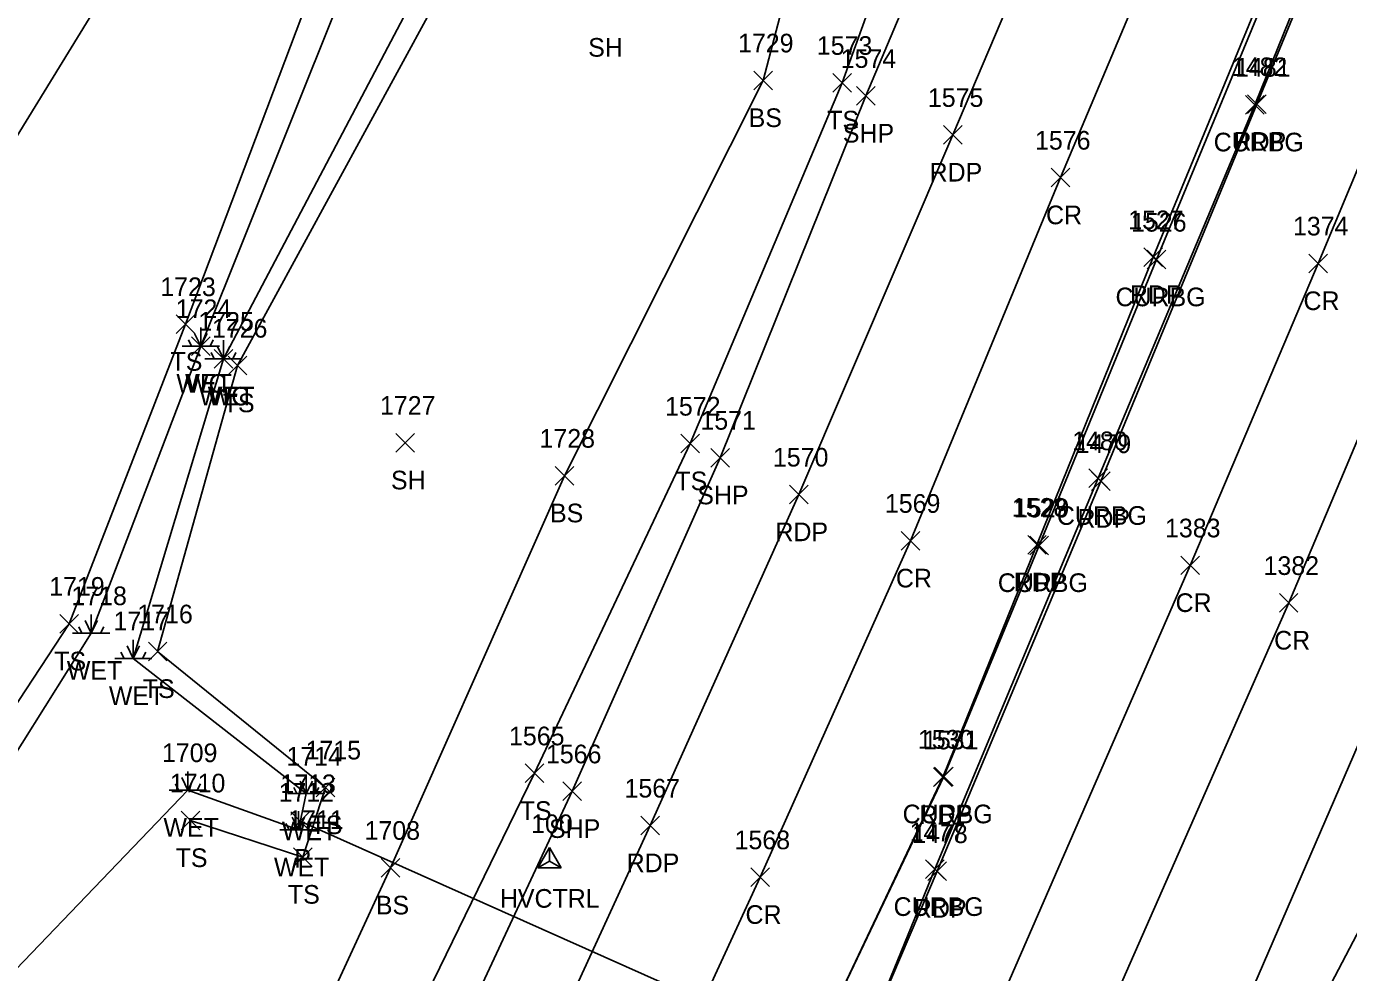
# Model space of a CAD drawing. Extents: x 1623612 to 1625808, y 621345 to 627748.
# Drawn here: x 1624457.2 to 1624599, y 625894.9 to 625996.3 of the extents above; entities that cross this region are included whole.
import ezdxf

# ---------------------------------------------------------------- set-up
doc = ezdxf.new("R2010")
doc.units = 0
for name, color, linetype in [('C_A', 7, 'Continuous'), ('C_I', 7, 'Continuous'), ('CPSM', 7, 'Continuous'), ('D_A', 7, 'Continuous'), ('D_I', 7, 'Continuous'), ('D_TIC', 7, 'Continuous'), ('DCP', 7, 'Continuous'), ('L_A', 7, 'Continuous'), ('L_I', 7, 'Continuous'), ('L_TIC', 7, 'Continuous'), ('LAWE', 7, 'Continuous'), ('LELB', 7, 'Continuous'), ('LFNC', 7, 'Continuous'), ('LSOGP', 7, 'Continuous'), ('LWET', 7, 'Continuous'), ('P_A', 7, 'Continuous'), ('P_I', 7, 'Continuous'), ('P_TIC', 7, 'Continuous'), ('PET', 7, 'Continuous'), ('PRC', 7, 'Continuous'), ('PSP', 7, 'Continuous'), ('R_A', 7, 'Continuous'), ('R_I', 7, 'Continuous'), ('R_TIC', 7, 'Continuous'), ('RC', 7, 'Continuous')]:
    doc.layers.add(name, color=color, linetype=linetype)

msp = doc.modelspace()

# ---------------------------------------------------------------- linework, layer by layer
at = {"layer": 'CPSM'}
for p, q in [((1624512.03, 625906.07), (1624513.28, 625908.24)), ((1624514.53, 625906.07), (1624513.28, 625908.24)), ((1624513.28, 625906.8), (1624513.28, 625908.24)), ((1624512.03, 625906.07), (1624513.28, 625906.8)), ((1624512.03, 625906.07), (1624514.53, 625906.07)), ((1624513.28, 625906.8), (1624513.28, 625906.8)), ((1624513.28, 625906.8), (1624514.53, 625906.07))]:
    msp.add_line(p, q, dxfattribs=at)
at = {"layer": 'D_TIC'}
for points in [[(1624485.55, 625910.08), (1624487.55, 625912.08)], [(1624487.55, 625910.08), (1624485.55, 625912.08)]]:
    msp.add_lwpolyline(points, dxfattribs=at)
at = {"layer": 'DCP'}
msp.add_lwpolyline([(1624543.09, 625885.86), (1624486.55, 625911.08)], dxfattribs=at)
at = {"layer": 'L_TIC'}
for points in [[(1624535.21, 625989.48), (1624537.21, 625991.48)], [(1624537.21, 625989.48), (1624535.21, 625991.48)], [(1624543.66, 625989.22), (1624545.66, 625991.22)], [(1624545.66, 625989.22), (1624543.66, 625991.22)], [(1624473.24, 625963.36), (1624475.24, 625965.36)], [(1624475.24, 625963.36), (1624473.24, 625965.36)], [(1624474.9, 625961), (1624476.9, 625963)], [(1624476.9, 625961), (1624474.9, 625963)], [(1624477.34, 625959.64), (1624479.34, 625961.64)], [(1624479.34, 625959.64), (1624477.34, 625961.64)], [(1624478.84, 625958.91), (1624480.84, 625960.91)], [(1624480.84, 625958.91), (1624478.84, 625960.91)], [(1624496.8, 625950.64), (1624498.8, 625952.64)], [(1624498.8, 625950.64), (1624496.8, 625952.64)], [(1624527.38, 625950.55), (1624529.38, 625952.55)], [(1624529.38, 625950.55), (1624527.38, 625952.55)], [(1624513.91, 625947.11), (1624515.91, 625949.11)], [(1624515.91, 625947.11), (1624513.91, 625949.11)], [(1624460.77, 625931.24), (1624462.77, 625933.24)], [(1624462.77, 625931.24), (1624460.77, 625933.24)], [(1624470.27, 625928.28), (1624472.27, 625930.28)], [(1624472.27, 625928.28), (1624470.27, 625930.28)], [(1624510.69, 625915.21), (1624512.69, 625917.21)], [(1624512.69, 625915.21), (1624510.69, 625917.21)], [(1624488.26, 625913.69), (1624490.26, 625915.69)], [(1624490.26, 625913.69), (1624488.26, 625915.69)], [(1624473.79, 625910.16), (1624475.79, 625912.16)], [(1624475.79, 625910.16), (1624473.79, 625912.16)], [(1624485.83, 625906.23), (1624487.83, 625908.23)], [(1624487.83, 625906.23), (1624485.83, 625908.23)], [(1624495.23, 625905.08), (1624497.23, 625907.08)], [(1624497.23, 625905.08), (1624495.23, 625907.08)]]:
    msp.add_lwpolyline(points, dxfattribs=at)
at = {"layer": 'LAWE'}
for points in [[(1624478.34, 625960.64), (1624502.51, 626006.49), (1624510.02, 626033.48), (1624538.01, 626022.07), (1624539, 626026.11), (1624515.37, 626039.01), (1624525.82, 626080.12), (1624541.49, 626122.12), (1624557.13, 626161.32), (1624574.3, 626199.4), (1624588.96, 626242.23), (1624604.56, 626282.04), (1624612.69, 626318.46), (1624618.16, 626354.23), (1624633.32, 626339.44), (1624651.01, 626315.35), (1624653.64, 626319.94), (1624637.21, 626339.9), (1624620.54, 626359.04), (1624606.22, 626380.55), (1624599.51, 626405.02), (1624601.1, 626417.17), (1624599.39, 626418.68), (1624597.72, 626417.92)], [(1624475.9, 625962), (1624495.4, 626010.74), (1624513.45, 626053.64), (1624523.83, 626080.72), (1624539.75, 626122.53), (1624554.03, 626163.77), (1624569.78, 626201.47), (1624586.16, 626244.06), (1624600.64, 626283.77), (1624605.98, 626319.56), (1624614.72, 626357.4), (1624602.68, 626377.24), (1624598.91, 626387.68), (1624595.49, 626400.19), (1624596.27, 626415.38)]]:
    msp.add_lwpolyline(points, dxfattribs=at)
at = {"layer": 'LELB'}
for points in [[(1624405.5, 625728.14), (1624428.24, 625773.19), (1624451.7, 625813.41), (1624479.3, 625869.39), (1624496.23, 625906.08), (1624514.91, 625948.11), (1624536.21, 625990.48), (1624546.45, 626029.66), (1624561.04, 626063.21), (1624576.65, 626110.9), (1624590.48, 626147.32), (1624609.26, 626181.73), (1624628.06, 626219.01), (1624648.51, 626267.43), (1624661.85, 626303.08), (1624661.36, 626343.87), (1624651.86, 626347.04), (1624650.32, 626353.64), (1624652.97, 626362.16), (1624638.4, 626383.22), (1624618.17, 626397.94), (1624604.09, 626415.44)], [(1624375.32, 625803.31), (1624399.86, 625843.95), (1624436.39, 625893.65), (1624461.77, 625932.24), (1624474.24, 625964.36), (1624492.43, 626012.44), (1624506.84, 626058.35), (1624517.83, 626084.66), (1624533.25, 626127.2), (1624547.8, 626166.97), (1624564.84, 626204.52), (1624581.23, 626246.76), (1624598.57, 626285.31), (1624600.66, 626320.03), (1624610.19, 626356.83), (1624599.69, 626375.7), (1624596.69, 626386.19), (1624590.38, 626400.67)], [(1624474.79, 625911.16), (1624486.83, 625907.23), (1624489.26, 625914.69), (1624471.27, 625929.28), (1624479.84, 625959.91), (1624504.09, 626004.46), (1624515.23, 626027.37), (1624539.55, 626018.82), (1624542.04, 626026.15), (1624519.32, 626037.26), (1624532.33, 626078.05), (1624547.61, 626119.81), (1624564.25, 626158.84), (1624580.02, 626196.52), (1624593.61, 626237.98), (1624610.85, 626280.48), (1624618.75, 626317.35), (1624619.41, 626347.56)], [(1624414.82, 625722.7), (1624435.62, 625760.87), (1624453.7, 625797.23), (1624474.13, 625837.17), (1624493.41, 625878.76), (1624511.69, 625916.21), (1624528.38, 625951.55), (1624544.66, 625990.22), (1624558.02, 626027.25), (1624569.94, 626061.58), (1624576.34, 626070.61), (1624593.27, 626109.93), (1624608.95, 626149.66), (1624624.61, 626188.43), (1624639.61, 626224.64), (1624652.78, 626258.96), (1624662.63, 626284.81), (1624668.95, 626309.14), (1624669.8, 626328.28), (1624669.98, 626343.79)]]:
    msp.add_lwpolyline(points, dxfattribs=at)
at = {"layer": 'LFNC'}
msp.add_lwpolyline([(1624427.61, 625937.89), (1624449.98, 625974.47), (1624478.22, 626020.43), (1624495.88, 626064.36), (1624506.11, 626090.08), (1624523, 626131.63), (1624538.15, 626169.09), (1624554.88, 626209.48), (1624571.65, 626251.72), (1624567.39, 626290.68), (1624562.31, 626349.95), (1624561.25, 626380.14), (1624560.31, 626420.97), (1624559.52, 626449.49)], dxfattribs=at)
at = {"layer": 'LSOGP'}
msp.add_lwpolyline([(1624523, 626131.63), (1624506.11, 626090.08), (1624495.88, 626064.36), (1624478.22, 626020.43), (1624449.98, 625974.47), (1624427.61, 625937.89), (1624410.91, 625910.13), (1624379.58, 625859.99)], dxfattribs=at)
at = {"layer": 'LWET'}
for p, q in [((1624475.9, 625962), (1624475.9, 625964)), ((1624474.9, 625962), (1624474.57, 625962.67)), ((1624475.9, 625962), (1624475.23, 625963.34)), ((1624475.9, 625962), (1624476.57, 625963.34)), ((1624476.9, 625962), (1624477.23, 625962.67)), ((1624478.34, 625960.64), (1624478.34, 625962.64)), ((1624477.9, 625962), (1624473.9, 625962)), ((1624477.34, 625960.64), (1624477, 625961.31)), ((1624478.34, 625960.64), (1624477.67, 625961.97)), ((1624478.34, 625960.64), (1624479, 625961.97)), ((1624479.34, 625960.64), (1624479.67, 625961.31)), ((1624480.34, 625960.64), (1624476.34, 625960.64)), ((1624464.15, 625931.23), (1624464.15, 625933.23)), ((1624466.15, 625931.23), (1624462.15, 625931.23)), ((1624463.15, 625931.23), (1624462.81, 625931.9)), ((1624464.15, 625931.23), (1624463.48, 625932.57)), ((1624464.15, 625931.23), (1624464.81, 625932.57)), ((1624465.15, 625931.23), (1624465.48, 625931.9)), ((1624468.66, 625928.53), (1624467.99, 625929.86)), ((1624468.66, 625928.53), (1624468.66, 625930.53)), ((1624468.66, 625928.53), (1624469.33, 625929.86)), ((1624470.66, 625928.53), (1624466.66, 625928.53)), ((1624467.66, 625928.53), (1624467.33, 625929.19)), ((1624469.66, 625928.53), (1624469.99, 625929.19)), ((1624474.51, 625914.41), (1624473.85, 625915.75)), ((1624474.51, 625914.41), (1624474.51, 625916.41)), ((1624474.51, 625914.41), (1624475.18, 625915.75)), ((1624487.21, 625914.04), (1624487.21, 625916.04)), ((1624476.51, 625914.41), (1624472.51, 625914.41)), ((1624473.51, 625914.41), (1624473.18, 625915.08)), ((1624475.51, 625914.41), (1624475.85, 625915.08)), ((1624486.21, 625914.04), (1624485.87, 625914.7)), ((1624487.21, 625914.04), (1624486.54, 625915.37)), ((1624487.21, 625914.04), (1624487.87, 625915.37)), ((1624488.21, 625914.04), (1624488.54, 625914.7)), ((1624489.21, 625914.04), (1624485.21, 625914.04)), ((1624486.36, 625910.16), (1624485.7, 625911.49)), ((1624486.36, 625910.16), (1624486.36, 625912.16)), ((1624486.36, 625910.16), (1624487.03, 625911.49)), ((1624488.36, 625910.16), (1624484.36, 625910.16)), ((1624485.36, 625910.16), (1624485.03, 625910.83)), ((1624487.36, 625910.16), (1624487.7, 625910.83))]:
    msp.add_line(p, q, dxfattribs=at)
for points in [[(1624378.24, 625801.1), (1624404.77, 625840.83), (1624439.42, 625891.91), (1624464.15, 625931.23), (1624475.9, 625962)], [(1624362.47, 625753.11), (1624386.95, 625796), (1624412.3, 625837.76), (1624446.85, 625885.6), (1624474.51, 625914.41), (1624486.36, 625910.16), (1624487.21, 625914.04), (1624468.66, 625928.53), (1624478.34, 625960.64)]]:
    msp.add_lwpolyline(points, dxfattribs=at)
at = {"layer": 'P_TIC'}
for points in [[(1624546.22, 625987.82), (1624548.22, 625989.82)], [(1624548.22, 625987.82), (1624546.22, 625989.82)], [(1624588.16, 625986.94), (1624590.16, 625988.94)], [(1624590.16, 625986.94), (1624588.16, 625988.94)], [(1624555.56, 625983.64), (1624557.56, 625985.64)], [(1624557.56, 625983.64), (1624555.56, 625985.64)], [(1624567.1, 625979.06), (1624569.1, 625981.06)], [(1624569.1, 625979.06), (1624567.1, 625981.06)], [(1624577.04, 625970.53), (1624579.04, 625972.53)], [(1624579.04, 625970.53), (1624577.04, 625972.53)], [(1624594.71, 625969.86), (1624596.71, 625971.86)], [(1624596.71, 625969.86), (1624594.71, 625971.86)], [(1624530.6, 625949.04), (1624532.6, 625951.04)], [(1624532.6, 625949.04), (1624530.6, 625951.04)], [(1624571.42, 625946.53), (1624573.42, 625948.53)], [(1624573.42, 625946.53), (1624571.42, 625948.53)], [(1624539.03, 625945.09), (1624541.03, 625947.09)], [(1624541.03, 625945.09), (1624539.03, 625947.09)], [(1624551.01, 625940.13), (1624553.01, 625942.13)], [(1624553.01, 625940.13), (1624551.01, 625942.13)], [(1624564.57, 625939.71), (1624566.57, 625941.71)], [(1624566.57, 625939.71), (1624564.57, 625941.71)], [(1624581, 625937.5), (1624583, 625939.5)], [(1624583, 625937.5), (1624581, 625939.5)], [(1624591.56, 625933.47), (1624593.56, 625935.47)], [(1624593.56, 625933.47), (1624591.56, 625935.47)], [(1624554.47, 625914.78), (1624556.47, 625916.78)], [(1624556.47, 625914.78), (1624554.47, 625916.78)], [(1624514.71, 625913.28), (1624516.71, 625915.28)], [(1624516.71, 625913.28), (1624514.71, 625915.28)], [(1624523.08, 625909.61), (1624525.08, 625911.61)], [(1624525.08, 625909.61), (1624523.08, 625911.61)], [(1624534.88, 625904.07), (1624536.88, 625906.07)], [(1624536.88, 625904.07), (1624534.88, 625906.07)], [(1624553.88, 625904.73), (1624555.88, 625906.73)], [(1624555.88, 625904.73), (1624553.88, 625906.73)]]:
    msp.add_lwpolyline(points, dxfattribs=at)
at = {"layer": 'PET'}
for points in [[(1624425.67, 625715.65), (1624447.22, 625754.54), (1624466.36, 625791.08), (1624487.12, 625831.75), (1624506.3, 625871.9), (1624524.08, 625910.61), (1624540.03, 625946.09), (1624556.56, 625984.64), (1624572.71, 626022.65), (1624589.71, 626064.03), (1624605.99, 626104.3), (1624622.34, 626144.13), (1624637.91, 626182.32), (1624652.97, 626219.87), (1624666.22, 626252.76), (1624676.12, 626279.69), (1624681.8, 626301.06), (1624682.54, 626327.48), (1624678.38, 626346.43)], [(1624700.76, 626272.27), (1624689.28, 626244.04), (1624672.95, 626203.67), (1624657.22, 626165.07), (1624639.97, 626122.42), (1624626.87, 626089.89), (1624609.23, 626047.25), (1624593.09, 626008.04), (1624578.04, 625971.53), (1624565.57, 625940.71), (1624555.47, 625915.78), (1624541.27, 625885.85), (1624534.37, 625871.9), (1624518.06, 625838.28), (1624503.61, 625808.5), (1624484.54, 625771.45), (1624465.59, 625736.05), (1624447.42, 625703.06)], [(1624697.29, 626122.48), (1624678.78, 626081.29), (1624660.95, 626038.77), (1624644.98, 625998.6), (1624626.67, 625954.13), (1624613.79, 625925.45), (1624589.8, 625879.72), (1624567.17, 625838.88), (1624546.44, 625801.43), (1624529.95, 625769.7), (1624509.63, 625731.24), (1624490.24, 625695.36), (1624481.98, 625680.63)], [(1624460.07, 625693.53), (1624483.15, 625735.74), (1624499.1, 625765.66), (1624511.9, 625793.12), (1624522.35, 625825.42), (1624529.91, 625846.85), (1624536.42, 625862.69), (1624541.8, 625875.32), (1624543.5, 625883.34), (1624544.97, 625882.88), (1624547, 625887.27), (1624554.88, 625905.73), (1624572.42, 625947.53), (1624589.16, 625987.94), (1624606.66, 626030.36), (1624622.98, 626070.33), (1624637.54, 626106.17)]]:
    msp.add_lwpolyline(points, dxfattribs=at)
at = {"layer": 'PRC'}
for points in [[(1624436.82, 625709.28), (1624458.78, 625749.62), (1624477.65, 625785.2), (1624498.86, 625827.51), (1624517.91, 625866.07), (1624535.88, 625905.07), (1624552.01, 625941.13), (1624568.1, 625980.06), (1624584.2, 626018.31), (1624601.56, 626060.15), (1624617.86, 626100.59), (1624633.9, 626140.47), (1624649.73, 626177.64), (1624664.57, 626215.84), (1624677.89, 626248.35), (1624689.08, 626275.05), (1624700.91, 626304.1), (1624709.94, 626325.53), (1624717.47, 626344.65), (1624728.1, 626371.26)], [(1624746.78, 626345.22), (1624728.92, 626300.56), (1624706.67, 626243.05), (1624691.9, 626206.9), (1624679.69, 626176.67), (1624663.83, 626137.95), (1624646.8, 626096.72), (1624629.43, 626053.71), (1624612.52, 626011.13), (1624595.71, 625970.86), (1624582, 625938.5), (1624560.77, 625889.8), (1624542.51, 625851.97), (1624524.08, 625812.63), (1624507.8, 625782.03)], [(1624756.75, 626332.96), (1624737.87, 626288.85), (1624717.83, 626237.45), (1624702.63, 626201.76), (1624690.94, 626172.24), (1624674.42, 626133.37), (1624657.37, 626090.13), (1624639.98, 626048.33), (1624623.77, 626007.33), (1624605.45, 625965.01), (1624592.56, 625934.47), (1624571.33, 625886.27), (1624551.87, 625847.8), (1624534.65, 625807.4), (1624518.3, 625775.7), (1624498.78, 625736.03), (1624480.71, 625702.14), (1624471.41, 625686.57)], [(1624760.82, 626312.53), (1624746.49, 626278.01), (1624728.27, 626233.28), (1624713.29, 626195.84), (1624701.88, 626168.74), (1624685.25, 626128.21), (1624667.86, 626085.49), (1624650.83, 626043.68), (1624633.95, 626002.72), (1624616.32, 625959.56), (1624604.63, 625929.9), (1624583.74, 625881.7), (1624564.37, 625840.79), (1624546.44, 625801.43)]]:
    msp.add_lwpolyline(points, dxfattribs=at)
at = {"layer": 'PSP'}
msp.add_lwpolyline([(1624417.68, 625720.8), (1624438.84, 625759.11), (1624458.11, 625795.15), (1624478.38, 625835.72), (1624497.98, 625876.28), (1624515.71, 625914.28), (1624531.6, 625950.04), (1624547.22, 625988.82), (1624563.29, 626026.94), (1624580.72, 626068.16), (1624597.18, 626108), (1624613.35, 626148.06), (1624629.33, 626186.41), (1624644.21, 626222.86), (1624657.67, 626256.77), (1624667.93, 626283.18), (1624675.15, 626305.88), (1624676.55, 626327.48), (1624673.72, 626344.86)], dxfattribs=at)
at = {"layer": 'R_TIC'}
for points in [[(1624587.93, 625986.87), (1624589.93, 625988.87)], [(1624589.93, 625986.87), (1624587.93, 625988.87)], [(1624577.4, 625970.27), (1624579.4, 625972.27)], [(1624579.4, 625970.27), (1624577.4, 625972.27)], [(1624571.12, 625946.84), (1624573.12, 625948.84)], [(1624573.12, 625946.84), (1624571.12, 625948.84)], [(1624564.79, 625939.64), (1624566.79, 625941.64)], [(1624566.79, 625939.64), (1624564.79, 625941.64)], [(1624554.58, 625914.85), (1624556.58, 625916.85)], [(1624556.58, 625914.85), (1624554.58, 625916.85)], [(1624553.6, 625904.92), (1624555.6, 625906.92)], [(1624555.6, 625904.92), (1624553.6, 625906.92)]]:
    msp.add_lwpolyline(points, dxfattribs=at)
at = {"layer": 'RC'}
for points in [[(1624700.99, 626272.06), (1624689.6, 626244.03), (1624673.22, 626203.62), (1624657.61, 626165.02), (1624640.13, 626122.2), (1624627.02, 626089.91), (1624609.59, 626047.26), (1624593.5, 626007.85), (1624578.4, 625971.27), (1624565.79, 625940.64), (1624555.58, 625915.85), (1624541.27, 625885.85), (1624534.86, 625871.82), (1624518.48, 625838.05), (1624503.94, 625808.16), (1624484.9, 625771.28), (1624465.88, 625735.89), (1624447.8, 625702.94)], [(1624547, 625887.27), (1624554.6, 625905.92), (1624572.12, 625947.84), (1624588.93, 625987.87), (1624606.24, 626030.63), (1624622.62, 626070.4), (1624637.36, 626106.36), (1624639.98, 626113.52)]]:
    msp.add_lwpolyline(points, dxfattribs=at)

# ---------------------------------------------------------------- texts
at = {"layer": 'C_A'}
msp.add_text('HVCTRL', height=2, dxfattribs=at).set_placement((1624507.97, 625901.8))
at = {"layer": 'C_I'}
msp.add_text('100', height=2, dxfattribs=at).set_placement((1624511.32, 625909.8))
at = {"layer": 'D_A'}
msp.add_text('P', height=2, dxfattribs=at).set_placement((1624485.93, 625906.08))
at = {"layer": 'D_I'}
msp.add_text('1713', height=2, dxfattribs=at).set_placement((1624484.43, 625914.08))
at = {"layer": 'L_A'}
for s, p in [('SH', (1624517.44, 625993.02)), ('BS', (1624534.65, 625985.48)), ('TS', (1624543.07, 625985.22)), ('TS', (1624472.65, 625959.36)), ('WET', (1624473.28, 625957)), ('WC', (1624474.21, 625957)), ('WET', (1624475.71, 625955.64)), ('WC', (1624476.64, 625955.64)), ('TS', (1624478.25, 625954.91)), ('SH', (1624496.29, 625946.64)), ('TS', (1624526.79, 625946.55)), ('BS', (1624513.35, 625943.11)), ('TS', (1624460.18, 625927.24)), ('WET', (1624461.53, 625926.23)), ('WET', (1624466.04, 625923.53)), ('TS', (1624469.68, 625924.28)), ('TS', (1624510.1, 625911.21)), ('WET', (1624471.89, 625909.41)), ('TS', (1624487.67, 625909.69)), ('WET', (1624484.58, 625909.04)), ('TS', (1624473.2, 625906.16)), ('WET', (1624483.74, 625905.16)), ('TS', (1624485.24, 625902.23)), ('BS', (1624494.67, 625901.08))]:
    msp.add_text(s, height=2, dxfattribs=at).set_placement(p)
at = {"layer": 'L_I'}
for s, p in [('1729', (1624533.51, 625993.48)), ('1573', (1624541.96, 625993.22)), ('1723', (1624471.55, 625967.36)), ('1724', (1624473.21, 625965)), ('1724', (1624473.21, 625965)), ('1725', (1624475.64, 625963.64)), ('1725', (1624475.64, 625963.64)), ('1726', (1624477.09, 625962.91)), ('1727', (1624495.11, 625954.64)), ('1572', (1624525.68, 625954.55)), ('1728', (1624512.22, 625951.11)), ('1719', (1624459.64, 625935.24)), ('1718', (1624462.02, 625934.23)), ('1716', (1624469.09, 625932.28)), ('1717', (1624466.53, 625931.53)), ('1565', (1624508.95, 625919.21)), ('1709', (1624471.73, 625917.41)), ('1714', (1624485.08, 625917.04)), ('1715', (1624487.13, 625917.69)), ('1710', (1624472.58, 625914.16)), ('1712', (1624484.24, 625913.16)), ('1711', (1624485.27, 625910.23)), ('1708', (1624493.46, 625909.08))]:
    msp.add_text(s, height=2, dxfattribs=at).set_placement(p)
at = {"layer": 'P_A'}
for s, p in [('SHP', (1624544.75, 625983.82)), ('RDP', (1624586.65, 625982.94)), ('RDP', (1624554.05, 625979.64)), ('CR', (1624566.54, 625975.06)), ('RDP', (1624575.53, 625966.53)), ('CR', (1624594.15, 625965.86)), ('SHP', (1624529.14, 625945.04)), ('RDP', (1624569.91, 625942.53)), ('RDP', (1624537.52, 625941.09)), ('CR', (1624550.44, 625936.13)), ('RDP', (1624563.06, 625935.71)), ('CR', (1624580.43, 625933.5)), ('CR', (1624591, 625929.47)), ('RDP', (1624552.96, 625910.78)), ('SHP', (1624513.24, 625909.28)), ('RDP', (1624521.57, 625905.61)), ('CR', (1624534.31, 625900.07)), ('RDP', (1624552.37, 625900.73))]:
    msp.add_text(s, height=2, dxfattribs=at).set_placement(p)
at = {"layer": 'P_I'}
for s, p in [('1574', (1624544.52, 625991.82)), ('1482', (1624586.47, 625990.94)), ('1575', (1624553.87, 625987.64)), ('1576', (1624565.36, 625983.06)), ('1527', (1624575.35, 625974.53)), ('1374', (1624593.02, 625973.86)), ('1571', (1624529.48, 625953.04)), ('1479', (1624569.72, 625950.53)), ('1570', (1624537.25, 625949.09)), ('1569', (1624549.26, 625944.13)), ('1528', (1624562.88, 625943.71)), ('1383', (1624579.3, 625941.5)), ('1382', (1624589.87, 625937.47)), ('1531', (1624553.34, 625918.78)), ('1566', (1624512.91, 625917.28)), ('1567', (1624521.34, 625913.61)), ('1568', (1624533.14, 625908.07)), ('1478', (1624552.19, 625908.73))]:
    msp.add_text(s, height=2, dxfattribs=at).set_placement(p)
at = {"layer": 'R_A'}
for p in [(1624584.52, 625982.87), (1624573.99, 625966.27), (1624567.7, 625942.84), (1624561.37, 625935.64), (1624551.16, 625910.85), (1624550.19, 625900.92)]:
    msp.add_text('CURBG', height=2, dxfattribs=at).set_placement(p)
at = {"layer": 'R_I'}
for s, p in [('1481', (1624586.81, 625990.87)), ('1526', (1624575.66, 625974.27)), ('1480', (1624569.34, 625950.84)), ('1529', (1624563.09, 625943.64)), ('1530', (1624552.8, 625918.85)), ('1477', (1624551.91, 625908.92))]:
    msp.add_text(s, height=2, dxfattribs=at).set_placement(p)

doc.saveas('drawing.dxf')
